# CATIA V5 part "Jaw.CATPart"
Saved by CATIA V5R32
Part number: Part 2
Bounding box of the stored display mesh (mm): x 0 to 20, y -45 to 45, z -25 to 40
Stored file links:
  D:\PROJECTS\Project 2022\CATIA V5 6R 2022\Resources\Part Files\c16_catia_v5_6r2022_prt\Prismatic Joint-(Fig16-14)\Jaw.CATPart
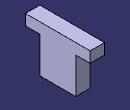
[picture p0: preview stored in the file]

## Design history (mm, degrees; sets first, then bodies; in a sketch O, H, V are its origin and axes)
Body1 (main body)
  Sketch1 on yz-plane, origin (0, 0, 0), H (0, 1, 0), V (0, 0, 1)
    line L1 (25, 25) -> (25, -25)
    line L2 (25, -25) -> (-25, -25)
    line L3 (-25, -25) -> (-25, 25)
    point P1 (25, 25)
    point P4 (-25, 25)
    line L4 (-25, 25) -> (-45, 25)
    point P5 (-45, 25)
    line L5 (-45, 25) -> (-45, 40)
    line L6 (-45, 40) -> (45, 40)
    line L7 (25, 25) -> (45, 25)
    point P8 (45, 25)
    line L8 (45, 25) -> (45, 40)
    reference intersected line E1 through (0, 0) direction (-1, 0) from xy-plane
    reference intersected line E3 through (0, 0) direction (0, 1) from zx-plane
    length L1 = 50
    distance V L1 = 25
    distance H L2 = 25
    distance E1 L6 = 40
    distance P1 P8 = 20
    distance P4 P5 = 20
    vertical: L1 V, L3 V, L5 V, L8 V, E3 V
    horizontal: L2 H, L4 H, L6 H, L7 H, E1 H
    equidistance: L1 L3 O
    perpendicularity: E1 L1
    coincidence: P1 L4, P4 L7, P5 L7, P8 L4, L4 L7
  Pad1: profile Sketch1, direction (1, 0, 0), length 20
